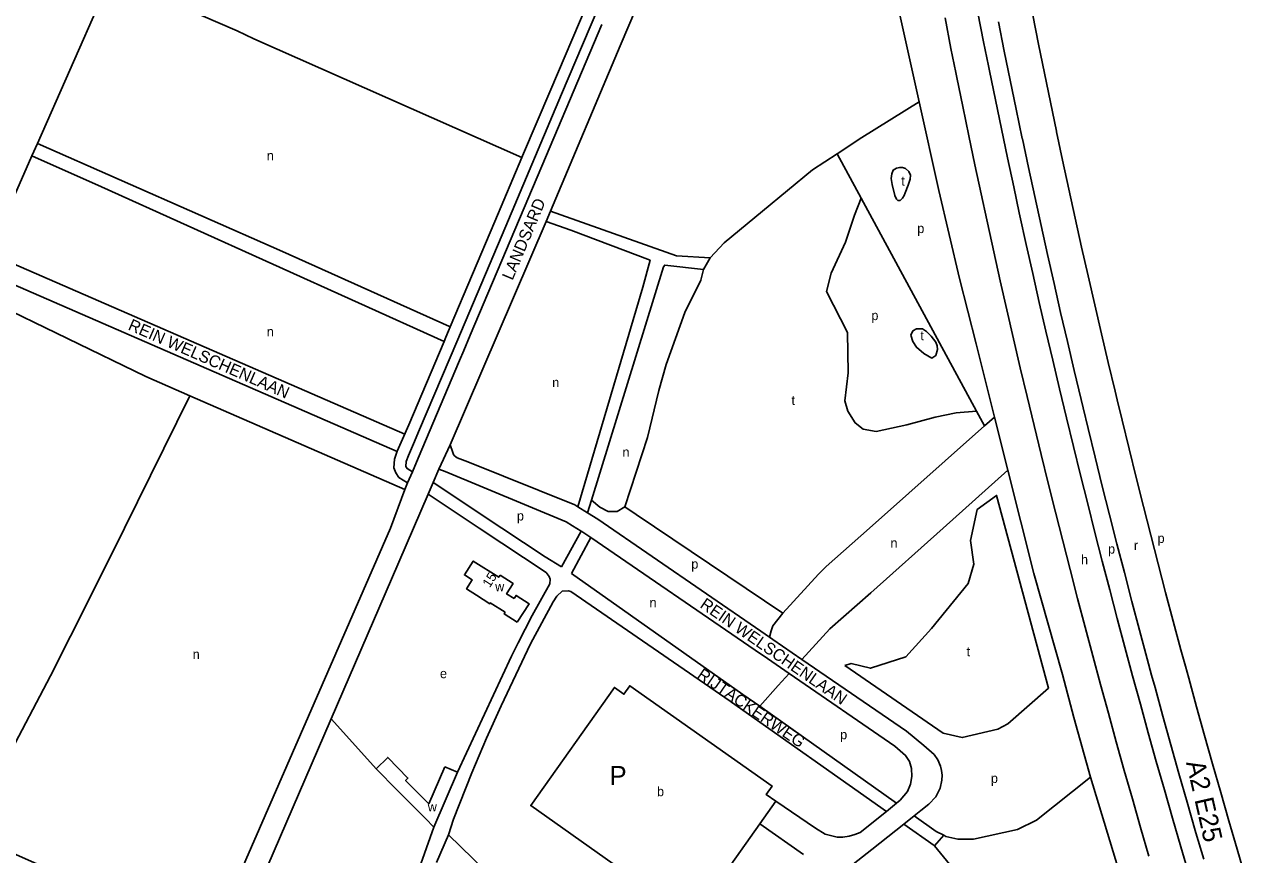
# Model space of a CAD drawing. Extents: x 155317 to 156514, y 385353 to 386894.
# Drawn here: x 155844 to 156360, y 386029 to 386379 of the extents above; entities that cross this region are included whole.
import ezdxf

# ---------------------------------------------------------------- set-up
doc = ezdxf.new("R2010")
doc.units = 0
for name, color, linetype in [('BLT_Basislijn', 7, 'Continuous'), ('BLT_Bebouwing', 7, 'Continuous'), ('BLT_Centroide', 7, 'Continuous'), ('BLT_Huisnummer', 7, 'Continuous'), ('BLT_Plantopo', 7, 'Continuous'), ('BLT_Straatnaam', 7, 'Continuous'), ('BLT_Straatnaam_hoofdweg', 7, 'Continuous'), ('BLT_Tekst_parkeren', 7, 'Continuous'), ('BLT_Vlakafsluiter', 7, 'Continuous')]:
    doc.layers.add(name, color=color, linetype=linetype)

msp = doc.modelspace()

# ---------------------------------------------------------------- linework, layer by layer
at = {"layer": 'BLT_Basislijn'}
for p, q in [((155849.86, 386329.05), (155881.04, 386399.61)), ((156088.15, 386379.28), (156062.79, 386319.37)), ((155849.86, 386329.05), (155847.49, 386323.78)), ((156187.47, 386324.71), (156197.63, 386305.95)), ((156062.79, 386319.37), (156032.61, 386248.03)), ((156197.63, 386305.95), (156246.32, 386216.05)), ((156066.46, 386300.42), (156064.68, 386296.12)), ((156064.68, 386296.12), (156024.06, 386201.79)), ((156131.08, 386275.75), (156133.94, 386280.71)), ((156032.61, 386248.03), (156029.92, 386241.66)), ((156029.92, 386241.66), (156028.11, 386237.4)), ((156028.11, 386237.4), (156010.67, 386196.17)), ((155914.24, 386222.48), (156004.97, 386182.89)), ((156246.32, 386216.05), (156249.71, 386209.79)), ((156259.56, 386191.06), (156253.9, 386213.51)), ((156010.67, 386196.17), (156008.17, 386190.34)), ((156008.17, 386190.34), (156006.17, 386185.69)), ((156016.88, 386185.85), (156019.33, 386191.56)), ((156006.17, 386185.69), (156004.97, 386182.89)), ((156014.78, 386180.96), (156016.88, 386185.85)), ((156082.09, 386173.1), (156083.72, 386178.4)), ((156071.18, 386150.26), (156079.36, 386165.38)), ((156083.48, 386162.73), (156075.36, 386147.45)), ((156083.48, 386162.73), (156152.94, 386115.03)), ((155999.37, 386145.03), (155973.89, 386086.05)), ((156147.74, 386096.39), (156075.36, 386147.45)), ((156155.21, 386123.17), (156158.89, 386120.64)), ((156158.89, 386120.64), (156160.32, 386119.66)), ((156147.74, 386096.39), (156154.79, 386091.41)), ((156142.95, 386093.16), (156208.31, 386046.92)), ((156212.51, 386050.44), (156154.79, 386091.41)), ((155973.89, 386086.05), (155941.31, 386010.86)), ((155979.15, 386080.29), (155973.89, 386086.05)), ((155992.89, 386065.06), (155979.15, 386080.29)), ((156208.31, 386046.92), (156197.2, 386038.17)), ((156220.03, 386045.11), (156215.7, 386041.67)), ((156154.84, 386041.84), (156173.26, 386028.79)), ((156018.39, 386025.39), (156023.37, 386037.09)), ((156023.37, 386037.09), (156064.66, 385997.16)), ((156228.62, 386032.5), (156232.53, 386036.93))]:
    msp.add_line(p, q, dxfattribs=at)
for points in [[(156008.17, 386190.34), (156005.94, 386191.74), (156005.63, 386192.2), (156005.46, 386192.7), (156005.58, 386194.69), (156006.48, 386197.32), (156008.65, 386202.26), (156011.23, 386208.32), (156026.89, 386245.29), (156047.58, 386294.13), (156071.19, 386349.9), (156092.58, 386400.21), (156115.86, 386454.8), (156144.01, 386520.66), (156146.65, 386528.94), (156146.91, 386535.26), (156146.23, 386540.12), (156143.13, 386563.38), (156143.19, 386564.65), (156143.43, 386566.09)], [(156222.14, 386346.64), (156213.05, 386387.16), (156205.06, 386419.13), (156199.15, 386445.38), (156192.3, 386480.87), (156186.38, 386512.73), (156183.38, 386533.38), (156181.09, 386550.17), (156182.07, 386553.28)], [(156066.46, 386300.42), (156095.83, 386370.24), (156169.27, 386542.55)], [(156125.52, 386490.13), (156111.26, 386456.76), (156087.98, 386402.17), (156066.59, 386351.85), (156054.72, 386323.81), (156054.41, 386323.08)], [(155881.04, 386399.61), (155934.27, 386376.53), (155941.27, 386373.2), (156054.41, 386323.08)], [(156233.14, 386382), (156235.54, 386369.17), (156237.57, 386359.03), (156238.01, 386356.87), (156240.52, 386344.58), (156243.06, 386332.3), (156245.65, 386320.03), (156248.27, 386307.76), (156250.66, 386296.75), (156250.93, 386295.51), (156253.63, 386283.26), (156256.37, 386271.02), (156259.14, 386258.79), (156261.96, 386246.56), (156264.81, 386234.35), (156267.7, 386222.14), (156270.62, 386209.95), (156273.59, 386197.76), (156276.59, 386185.58), (156279.63, 386173.42), (156282.71, 386161.26), (156285.83, 386149.11), (156288.98, 386136.97), (156292.17, 386124.84), (156295.4, 386112.72), (156298.67, 386100.61), (156301.97, 386088.51), (156305.31, 386076.42), (156308.69, 386064.34), (156312.11, 386052.28), (156315.56, 386040.22), (156319.05, 386028.17)], [(156246.89, 386384.17), (156249.32, 386371.91), (156251.34, 386361.82), (156251.78, 386359.66), (156254.28, 386347.41), (156256.82, 386335.17), (156259.39, 386322.94), (156262.01, 386310.72), (156264.39, 386299.75), (156264.66, 386298.51), (156267.35, 386286.3), (156270.08, 386274.1), (156272.84, 386261.92), (156275.64, 386249.74), (156278.49, 386237.56), (156281.36, 386225.4), (156284.28, 386213.25), (156287.24, 386201.1), (156290.23, 386188.97), (156293.26, 386176.84), (156296.32, 386164.73), (156299.43, 386152.62), (156302.57, 386140.52), (156305.75, 386128.44), (156308.97, 386116.36), (156312.22, 386104.29), (156315.52, 386092.23), (156318.85, 386080.19), (156322.21, 386068.15), (156325.62, 386056.12), (156329.06, 386044.11), (156332.54, 386032.1), (156336.06, 386020.11)], [(156255.59, 386380.37), (156258.04, 386368.06), (156260.53, 386355.75), (156263.06, 386343.45), (156265.63, 386331.16), (156265.68, 386330.93), (156268.23, 386318.88), (156270.88, 386306.61), (156273.56, 386294.34), (156276.28, 386282.09), (156279.04, 386269.84), (156281.84, 386257.6), (156284.67, 386245.37), (156287.55, 386233.15), (156290.46, 386220.94), (156291.32, 386217.36), (156293.41, 386208.73), (156296.39, 386196.54), (156299.42, 386184.35), (156302.48, 386172.18), (156305.59, 386160.01), (156308.73, 386147.86), (156311.9, 386135.71), (156315.12, 386123.57), (156318.37, 386111.45), (156320.25, 386104.54), (156321.67, 386099.33), (156325, 386087.23), (156328.36, 386075.13), (156331.77, 386063.05), (156335.21, 386050.98), (156338.69, 386038.91), (156338.97, 386037.95), (156342.22, 386026.86)], [(156359.91, 386019.02), (156356.36, 386031.02), (156352.86, 386043.02), (156349.39, 386055.04), (156345.96, 386067.07), (156342.57, 386079.11), (156339.21, 386091.16), (156335.89, 386103.22), (156334.48, 386108.41), (156332.61, 386115.29), (156329.37, 386127.38), (156326.17, 386139.47), (156323, 386151.57), (156319.87, 386163.68), (156316.78, 386175.8), (156313.73, 386187.93), (156310.72, 386200.07), (156307.74, 386212.22), (156305.66, 386220.82), (156304.8, 386224.38), (156301.9, 386236.55), (156299.04, 386248.72), (156296.21, 386260.91), (156293.42, 386273.1), (156290.68, 386285.31), (156287.96, 386297.52), (156285.29, 386309.74), (156282.66, 386321.97), (156280.11, 386333.97), (156280.06, 386334.2), (156277.51, 386346.45), (156274.99, 386358.7), (156272.5, 386370.96), (156270.06, 386383.23)], [(156187.47, 386324.71), (156197.9, 386331.54), (156222.14, 386346.64)], [(156253.9, 386213.51), (156246.16, 386244.47), (156239.1, 386272.08), (156230.39, 386309.23), (156222.14, 386346.64)], [(155849.86, 386329.05), (155953.38, 386283.4), (156023.81, 386251.78), (156024.15, 386251.63)], [(155847.49, 386323.78), (155822.49, 386266.86), (155822.55, 386266.18)], [(155847.49, 386323.78), (155876.96, 386310.78), (156021.53, 386245.45)], [(156054.41, 386323.08), (156042.98, 386296.08), (156024.15, 386251.63)], [(156133.94, 386280.71), (156139.84, 386287.13), (156155.98, 386300.46), (156177.15, 386317.95), (156187.47, 386324.71)], [(156197.63, 386305.95), (156194.77, 386298.75), (156191.06, 386287.31), (156185.02, 386274.21), (156182.97, 386266.48), (156191.91, 386249.28), (156192.16, 386232.19), (156190.79, 386220.33), (156191.99, 386216.04), (156195.15, 386211.02), (156198.41, 386208.42), (156204, 386207.47), (156216.86, 386210.3), (156228.84, 386213.49), (156237.78, 386215.24), (156246.32, 386216.05)], [(156066.46, 386300.42), (156119.68, 386281.64), (156133.94, 386280.71)], [(156064.68, 386296.12), (156075.05, 386292.46), (156108.5, 386279.7), (156105.45, 386268.32), (156078.05, 386175.6)], [(156083.72, 386178.4), (156114.17, 386276.87), (156114.71, 386277.66), (156131.08, 386275.75)], [(156131.08, 386275.75), (156129.9, 386271.31), (156123.15, 386257.61), (156115.33, 386235.7), (156112.26, 386224.71), (156107.36, 386204.94), (156097.92, 386175.59)], [(155914.24, 386222.48), (155895.68, 386230.61), (155829.4, 386262.76)], [(156024.15, 386251.63), (156023.43, 386249.93), (156022.29, 386247.24), (156021.53, 386245.45)], [(156021.53, 386245.45), (156006.63, 386210.28), (156004.07, 386204.24), (156001.82, 386199.14), (156000.63, 386195.67), (156000.41, 386192.01), (156001.12, 386189.93), (156002.41, 386188.06), (156006.17, 386185.69)], [(155914.24, 386222.48), (155886.63, 386166.67), (155872.3, 386137.71)], [(156249.71, 386209.79), (156201.14, 386166.67), (156182.8, 386150.38), (156179.58, 386147.23), (156164.51, 386130.72)], [(156253.9, 386213.51), (156249.71, 386209.79)], [(156024.06, 386201.79), (156025.24, 386198.48), (156025.52, 386197.75), (156025.95, 386197.15), (156026.52, 386196.66), (156027.14, 386196.34), (156031.55, 386194.59), (156076.7, 386176.44), (156078.05, 386175.6)], [(156019.33, 386191.56), (156022.07, 386190.54), (156073.06, 386169.28), (156075.7, 386167.64), (156079.36, 386165.38)], [(156259.56, 386191.06), (156232.23, 386166.67), (156201.64, 386139.26), (156184.38, 386124.15), (156172.63, 386111.21)], [(156294.45, 386061.41), (156287.36, 386086.61), (156282.58, 386104.87), (156270.55, 386147.42), (156259.56, 386191.06)], [(156016.88, 386185.85), (156045.91, 386166.67), (156064.24, 386154.55), (156071.18, 386150.26)], [(156004.97, 386182.89), (155998.89, 386166.67), (155923.01, 385992.36), (155820.9, 386037.51)], [(155999.37, 386145.03), (156008.65, 386166.67), (156014.78, 386180.96)], [(156014.78, 386180.96), (156036.4, 386166.67), (156064.66, 386147.82), (156065.89, 386146.24), (156066.36, 386145.11), (156066.25, 386143.04), (156058.77, 386129.77), (156052.89, 386118.14)], [(156078.05, 386175.6), (156082.09, 386173.1)], [(156083.72, 386178.4), (156087.27, 386175.41), (156090.77, 386173.58), (156094.59, 386173.66), (156097.92, 386175.59)], [(156097.92, 386175.59), (156102.62, 386172.35), (156164.51, 386130.72)], [(156082.09, 386173.1), (156086.51, 386170.36), (156155.21, 386123.17)], [(156079.36, 386165.38), (156079.65, 386165.2), (156083.48, 386162.73)], [(155837.6, 386070.16), (155855.46, 386104.23), (155872.3, 386137.71)], [(156023.37, 386037.09), (156025.6, 386043.72), (156033.24, 386063.33), (156039.44, 386077.99), (156045.68, 386091.63), (156058.05, 386117.78), (156067.56, 386135.57), (156069.1, 386137.91), (156071.44, 386140.02), (156074.11, 386140.18), (156075.01, 386139.89), (156142.39, 386093.56), (156142.95, 386093.16)], [(156164.51, 386130.72), (156160.4, 386125.42), (156159.6, 386123.26), (156158.89, 386120.64)], [(156052.89, 386118.14), (156050.07, 386112.57), (156027.17, 386063.55)], [(156160.32, 386119.66), (156172.63, 386111.21)], [(156152.94, 386115.03), (156158.06, 386111.51)], [(156158.06, 386111.51), (156167.2, 386105.23)], [(156172.63, 386111.21), (156216.7, 386080.94), (156224.12, 386074.8), (156228.49, 386071.03), (156229.99, 386068.85), (156231.13, 386066.1), (156231.51, 386064.33), (156231.76, 386062.31), (156231.7, 386060.24), (156230.91, 386056.77), (156229.2, 386053.2), (156226.25, 386050.09), (156222.8, 386047.34), (156220.03, 386045.11)], [(156167.2, 386105.23), (156162.57, 386100.12), (156154.79, 386091.41)], [(156167.2, 386105.23), (156211.83, 386074.58), (156216.4, 386070.68), (156218.03, 386068.04), (156218.86, 386065.07), (156219.05, 386061.75), (156218.46, 386058.55), (156217.13, 386055.43), (156214.13, 386051.81), (156212.51, 386050.44)], [(156294.45, 386061.41), (156271.62, 386043.35), (156263.68, 386039.44), (156245.1, 386035.35), (156238.41, 386035.35), (156233.41, 386036.49), (156232.53, 386036.93)], [(156314.22, 385995.98), (156304.95, 386026.73), (156294.45, 386061.41)], [(156197.2, 386038.17), (156195.01, 386037.24), (156192.52, 386036.55), (156189.89, 386036.12), (156187.54, 386036.08), (156182.41, 386037.38), (156178.33, 386039.89), (156161.54, 386051.34)], [(156212.51, 386050.44), (156208.31, 386046.92)], [(156232.53, 386036.93), (156229.27, 386038.55), (156220.03, 386045.11)], [(155980.42, 385952.4), (155981.11, 385953.42), (156003.09, 386000.75), (156017.22, 386040.43)], [(156215.7, 386041.67), (156202.11, 386030.96), (156187.01, 386019.05)], [(156228.62, 386032.5), (156228.48, 386032.56), (156215.7, 386041.67)], [(156255.52, 385989.78), (156231.88, 386016.58), (156237.51, 386021.7), (156228.62, 386032.5)]]:
    msp.add_lwpolyline(points, dxfattribs=at)
for points in [[(156211.87, 386307.08), (156210.69, 386311.69), (156210.27, 386314.29), (156210.61, 386316.14), (156211.2, 386317.81), (156212.54, 386318.65), (156213.88, 386318.91), (156215.05, 386318.91), (156216.31, 386318.4), (156217.74, 386317.14), (156218.41, 386315.63), (156218.33, 386313.96), (156217.49, 386311.36), (156216.23, 386308.17), (156215.81, 386306.99), (156215.14, 386305.9), (156214.13, 386304.98), (156213.12, 386304.98), (156212.54, 386305.57)], [(156229.09, 386245.09), (156227.16, 386247.62), (156225.27, 386249.64), (156223.49, 386250.72), (156221.01, 386250.71), (156219.48, 386249.9), (156218.65, 386248.09), (156219.41, 386245.38), (156220.96, 386242.99), (156224.07, 386240.37), (156227.51, 386238.38), (156229.16, 386239.55), (156229.9, 386242), (156229.7, 386243.61)], [(156190.74, 386108.68), (156232.26, 386080.1), (156240.31, 386078.2), (156255.39, 386081.71), (156259.59, 386083.95), (156276.71, 386098.99), (156254.8, 386180.4), (156246.61, 386174.54), (156243.83, 386161.37), (156245.14, 386151.44), (156242.8, 386143.21), (156227.29, 386124.18), (156216.55, 386112.22), (156201.55, 386107.46), (156193.35, 386109.51)]]:
    msp.add_lwpolyline(points, close=True, dxfattribs=at)
at = {"layer": 'BLT_Bebouwing'}
for p, q in [((156021.84, 386065.85), (156027.17, 386063.55)), ((156027.17, 386063.55), (156017.22, 386040.43)), ((156154.84, 386041.84), (156161.54, 386051.34))]:
    msp.add_line(p, q, dxfattribs=at)
for points in [[(156047.35, 386131.07), (156041.05, 386135.06), (156040.84, 386134.72), (156035.27, 386138.26), (156031.05, 386140.94), (156033.46, 386144.75), (156030.17, 386146.85), (156033.87, 386152.68), (156044.62, 386145.86), (156045.17, 386146.73)], [(156045.17, 386146.73), (156050.71, 386143.21), (156047.95, 386138.87), (156051.1, 386136.88)], [(156052.42, 386126.92), (156057.41, 386134.67), (156051.94, 386138.19), (156051.1, 386136.88)], [(156047.35, 386131.07), (156046.94, 386130.42), (156052.42, 386126.92)], [(156161.54, 386051.34), (156157.51, 386054.17), (156160, 386057.7), (156099.96, 386100.04), (156097.49, 386096.49), (156093.46, 386099.39), (156058.17, 386049.45), (156092.94, 386024.92)], [(155992.89, 386065.06), (155997.77, 386069.82), (156006.31, 386061.06), (156005.3, 386060.07), (156015.11, 386050.23), (156021.84, 386065.85)], [(156017.22, 386040.43), (156013.69, 386043.98), (156001.7, 386056.03), (155992.89, 386065.06)], [(156104.28, 386016.92), (156126.3, 386001.39), (156154.84, 386041.84)]]:
    msp.add_lwpolyline(points, dxfattribs=at)
at = {"layer": 'BLT_Plantopo'}
for points in [[(156004.92, 386206.26), (155517.96, 386418.36), (155491.14, 386438.93), (155474.88, 386460.36), (155463.29, 386481.83), (155455.66, 386508.18), (155453.98, 386536.3), (155450.15, 386554.05), (155440.06, 386569.5), (155426.03, 386581.3)], [(156001.74, 386198.92), (155513.87, 386411.42), (155485.42, 386433.23), (155468.13, 386456.02), (155455.84, 386478.78), (155447.72, 386506.81), (155446.03, 386535.21), (155442.64, 386550.92), (155434.01, 386564.14), (155421.84, 386574.37)]]:
    msp.add_lwpolyline(points, dxfattribs=at)
at = {"layer": 'BLT_Vlakafsluiter'}
msp.add_line((156024.06, 386201.79), (156019.33, 386191.56), dxfattribs=at)

# ---------------------------------------------------------------- texts
at = {"layer": 'BLT_Centroide'}
for s, p in [('n', (155946.71, 386321.91)), ('t', (156214.56, 386311.19)), ('p', (156221.3, 386291.19)), ('p', (156201.93, 386254.44)), ('n', (155946.71, 386247.6)), ('t', (156222.61, 386245.96)), ('n', (156067.2, 386226.14)), ('t', (156168.22, 386218.58)), ('n', (156096.84, 386196.72)), ('p', (156052.29, 386169.83)), ('p', (156322.74, 386160.37)), ('n', (156209.99, 386158.37)), ('p', (156301.85, 386155.85)), ('r', (156312.76, 386157.36)), ('h', (156290.43, 386151.36)), ('p', (156125.9, 386149.5)), ('w', (156043.11, 386140)), ('n', (156108.27, 386133.22)), ('n', (155915.41, 386111.39)), ('t', (156242.11, 386112.5)), ('e', (156019.81, 386103.26)), ('p', (156188.75, 386077.48)), ('p', (156252.38, 386059.02)), ('b', (156111.44, 386053.45)), ('w', (156014.66, 386047))]:
    msp.add_text(s, height=4, dxfattribs=at).set_placement(p)
at = {"layer": 'BLT_Huisnummer'}
msp.add_text('15', height=4, rotation=57.6176, dxfattribs=at).set_placement((156040.83, 386141.21))
at = {"layer": 'BLT_Straatnaam'}
for s, rotation, p in [('LANDSARD', 67.2009, (156050.42, 386270.96)), ('REIN WELSCHENLAAN', 336.3352, (155887.8, 386250.56)), ('REIN WELSCHENLAAN', 325.3352, (156129.22, 386133.38)), ('RIJTACKERWEG', 325.5352, (156127.99, 386103.68))]:
    msp.add_text(s, height=5, rotation=rotation, dxfattribs=at).set_placement(p)
at = {"layer": 'BLT_Straatnaam_hoofdweg'}
msp.add_text('A2 E25', height=8, rotation=282.8014, dxfattribs=at).set_placement((156334.74, 386067.68))
at = {"layer": 'BLT_Tekst_parkeren'}
msp.add_text('P', height=8, dxfattribs=at).set_placement((156091.47, 386058.18))

doc.saveas('drawing.dxf')
